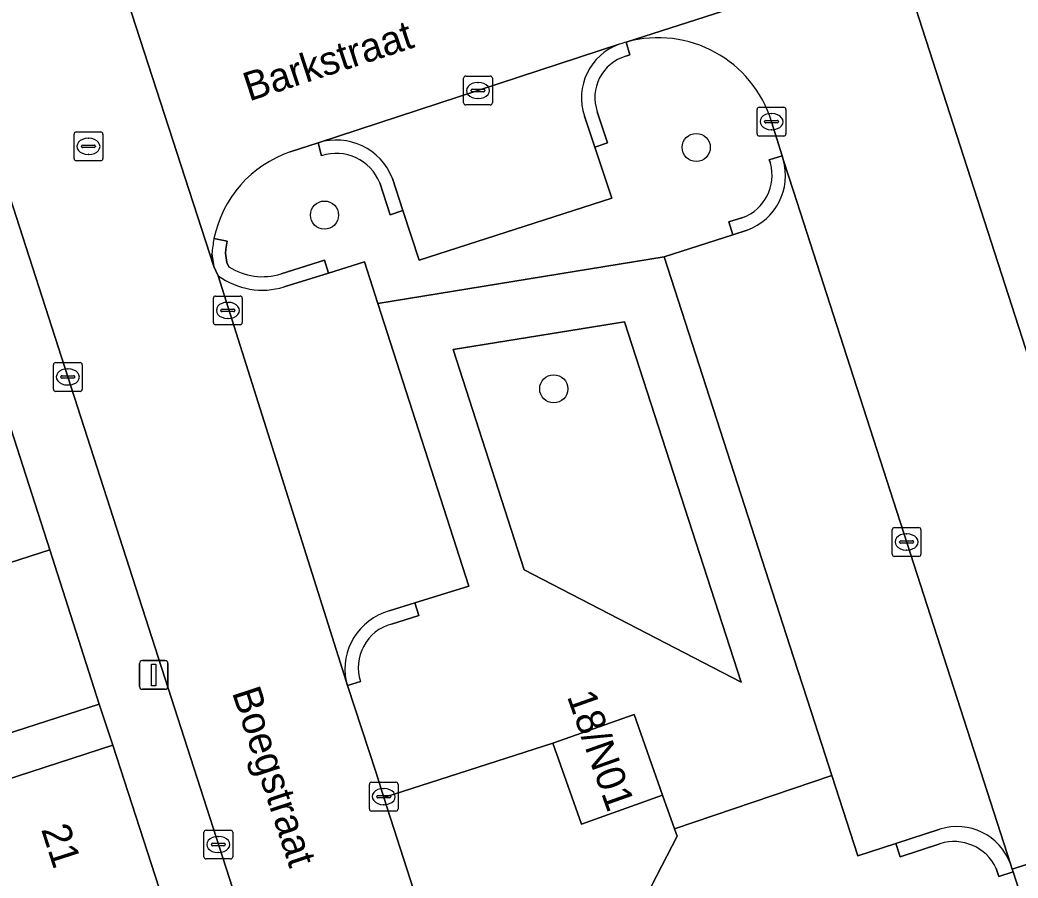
# Model space of a CAD drawing. Extents: x 159371 to 159986, y 382987 to 383597.
# Drawn here: x 159473.09 to 159507.81, y 383319.61 to 383349.44 of the extents above; entities that cross this region are included whole.
import ezdxf

# ---------------------------------------------------------------- set-up
doc = ezdxf.new("R2010")
doc.units = 0
for name, color, linetype in [('IMGEO_Boom', 7, 'Continuous'), ('IMGEO_Groenvoorziening', 7, 'Continuous'), ('IMGEO_Kolk', 7, 'Continuous'), ('IMGEO_Lichtmast', 7, 'Continuous'), ('IMGEO_Openbare_ruimte_label', 7, 'Continuous'), ('IMGEO_Pand', 7, 'Continuous'), ('IMGEO_Pand_nummerreeks', 7, 'Continuous'), ('IMGEO_Parkeervlak_open', 7, 'Continuous'), ('IMGEO_Rijbaan_lokaal_open', 7, 'Continuous'), ('IMGEO_Rioolput', 7, 'Continuous'), ('IMGEO_Voetpad_open', 7, 'Continuous')]:
    doc.layers.add(name, color=color, linetype=linetype)

msp = doc.modelspace()

# ---------------------------------------------------------------- linework, layer by layer
at = {"layer": 'IMGEO_Boom'}
for centre in [(159496.617, 383345.01), (159483.685, 383342.659), (159491.659, 383336.618)]:
    msp.add_circle(centre, 0.489, dxfattribs=at)
at = {"layer": 'IMGEO_Groenvoorziening'}
for points in [[(159494.182, 383348.675), (159494.307, 383348.225), (159494.162, 383348.182)], [(159493.175, 383346.249), (159493.532, 383345.171), (159493.089, 383345.024), (159493.677, 383343.248), (159486.984, 383341.088), (159486.415, 383342.814)], [(159499.196, 383344.46), (159499.156, 383344.583), (159499.601, 383344.723), (159499.237, 383345.904)], [(159483.583, 383344.719), (159483.466, 383345.171), (159482.492, 383344.854)], [(159486.415, 383342.814), (159485.972, 383342.668), (159485.606, 383343.777)], [(159482.176, 383340.618), (159483.687, 383341.089), (159483.826, 383340.644), (159485.072, 383341.032), (159485.541, 383339.58), (159495.497, 383341.203), (159497.889, 383341.976), (159497.745, 383342.42), (159498.235, 383342.578)], [(159479.841, 383341.841), (159480.298, 383341.748), (159480.273, 383341.609), (159480.253, 383341.469), (159480.239, 383341.329), (159480.288, 383341.009), (159480.358, 383340.862)], [(159500.626, 383325.36), (159500, 383327.293), (159495.497, 383341.203), (159485.541, 383339.58), (159488.71, 383329.763), (159486.828, 383329.174), (159486.966, 383328.732), (159486.014, 383328.439)], [(159484.933, 383326.446), (159484.484, 383326.299), (159485.48, 383323.262), (159485.755, 383322.408), (159491.627, 383324.299), (159494.453, 383325.298), (159495.447, 383322.487), (159495.858, 383321.325), (159501.334, 383323.171), (159500.626, 383325.36)], [(159505.094, 383320.803), (159503.712, 383320.352), (159503.564, 383320.811), (159502.237, 383320.383), (159501.334, 383323.171), (159495.858, 383321.325), (159495.949, 383321.067), (159494.157, 383317.584), (159497.271, 383315.986), (159500, 383316.88), (159501.761, 383317.457), (159503.231, 383313.074), (159509.191, 383315.017), (159508.463, 383317.266), (159507.635, 383319.824)], [(159507.635, 383319.824), (159507.142, 383319.664), (159507.051, 383319.945)]]:
    msp.add_lwpolyline(points, dxfattribs=at)
for points in [[(159498.18, 383326.423), (159494.123, 383338.953), (159488.159, 383337.981), (159490.629, 383330.329)], [(159490.629, 383330.329), (159488.159, 383337.981), (159494.123, 383338.953), (159498.18, 383326.423)]]:
    msp.add_lwpolyline(points, close=True, dxfattribs=at)
for centre, radius, start, end in [((159495.287, 383344.694), 4.131, 17.0256, 105.514), ((159494.593, 383346.744), 1.502, 106.674, 199.2278), ((159483.788, 383341.041), 4.027, 108.7711, 168.5427), ((159484.1, 383343.185), 1.619, 21.4513, 108.6111), ((159497.695, 383344.04), 1.559, 290.2668, 15.633), ((159481.524, 383342.657), 2.14, 236.9844, 287.7273), ((159486.428, 383326.925), 1.57, 105.2983, 197.751), ((159505.582, 383319.256), 1.622, 25.1356, 107.5166)]:
    msp.add_arc(centre, radius, start, end, dxfattribs=at)
at = {"layer": 'IMGEO_Kolk'}
for p, q in [((159488.6, 383347.49), (159489.452, 383347.49)), ((159488.525, 383346.564), (159488.525, 383347.416)), ((159489.013, 383347.27), (159489.038, 383347.27)), ((159489.526, 383347.416), (159489.526, 383346.564)), ((159488.784, 383346.984), (159488.784, 383346.996)), ((159489.222, 383346.947), (159488.824, 383346.947)), ((159488.827, 383347.033), (159489.225, 383347.033)), ((159489.268, 383346.996), (159489.268, 383346.984)), ((159489.452, 383346.49), (159488.6, 383346.49)), ((159489.036, 383346.71), (159489.011, 383346.71)), ((159498.809, 383346.407), (159499.661, 383346.407)), ((159498.734, 383345.481), (159498.734, 383346.333)), ((159499.222, 383346.187), (159499.247, 383346.187)), ((159499.735, 383346.333), (159499.735, 383345.481)), ((159498.993, 383345.901), (159498.993, 383345.913)), ((159499.431, 383345.864), (159499.033, 383345.864)), ((159499.036, 383345.95), (159499.434, 383345.95)), ((159499.477, 383345.913), (159499.477, 383345.901)), ((159499.661, 383345.407), (159498.809, 383345.407)), ((159499.245, 383345.627), (159499.22, 383345.627)), ((159479.898, 383339.845), (159480.75, 383339.845)), ((159479.823, 383338.919), (159479.823, 383339.771)), ((159480.311, 383339.625), (159480.336, 383339.625)), ((159480.824, 383339.771), (159480.824, 383338.919)), ((159480.082, 383339.339), (159480.082, 383339.351)), ((159480.52, 383339.302), (159480.122, 383339.302)), ((159480.125, 383339.388), (159480.523, 383339.388)), ((159480.566, 383339.351), (159480.566, 383339.339)), ((159480.75, 383338.845), (159479.898, 383338.845)), ((159480.334, 383339.065), (159480.309, 383339.065)), ((159474.256, 383336.605), (159474.256, 383337.457)), ((159474.331, 383337.531), (159475.183, 383337.531)), ((159475.257, 383337.457), (159475.257, 383336.605)), ((159474.515, 383337.025), (159474.515, 383337.037)), ((159474.558, 383337.074), (159474.956, 383337.074)), ((159474.744, 383337.311), (159474.769, 383337.311)), ((159474.999, 383337.037), (159474.999, 383337.025)), ((159474.953, 383336.988), (159474.555, 383336.988)), ((159474.767, 383336.751), (159474.742, 383336.751)), ((159475.183, 383336.531), (159474.331, 383336.531)), ((159503.432, 383330.868), (159503.432, 383331.72)), ((159503.507, 383331.794), (159504.359, 383331.794)), ((159503.92, 383331.574), (159503.945, 383331.574)), ((159504.433, 383331.72), (159504.433, 383330.868)), ((159503.691, 383331.288), (159503.691, 383331.3)), ((159504.129, 383331.251), (159503.731, 383331.251)), ((159503.734, 383331.337), (159504.132, 383331.337)), ((159504.175, 383331.3), (159504.175, 383331.288)), ((159504.359, 383330.794), (159503.507, 383330.794)), ((159503.943, 383331.014), (159503.918, 383331.014)), ((159485.245, 383322.014), (159485.245, 383322.866)), ((159485.32, 383322.94), (159486.172, 383322.94)), ((159486.246, 383322.866), (159486.246, 383322.014)), ((159485.547, 383322.483), (159485.945, 383322.483)), ((159485.733, 383322.72), (159485.758, 383322.72)), ((159485.504, 383322.434), (159485.504, 383322.446)), ((159485.942, 383322.397), (159485.544, 383322.397)), ((159485.756, 383322.16), (159485.731, 383322.16)), ((159485.988, 383322.446), (159485.988, 383322.434)), ((159486.172, 383321.94), (159485.32, 383321.94)), ((159479.491, 383320.348), (159479.491, 383321.2)), ((159479.566, 383321.274), (159480.418, 383321.274)), ((159480.492, 383321.2), (159480.492, 383320.348)), ((159479.75, 383320.768), (159479.75, 383320.78)), ((159480.188, 383320.731), (159479.79, 383320.731)), ((159479.793, 383320.817), (159480.191, 383320.817)), ((159479.979, 383321.054), (159480.004, 383321.054)), ((159480.234, 383320.78), (159480.234, 383320.768)), ((159480.002, 383320.494), (159479.977, 383320.494)), ((159480.418, 383320.274), (159479.566, 383320.274))]:
    msp.add_line(p, q, dxfattribs=at)
for points in [[(159488.6, 383347.49), (159489.452, 383347.49)], [(159488.525, 383346.564), (159488.525, 383347.416)], [(159489.526, 383347.416), (159489.526, 383346.564)], [(159489.452, 383346.49), (159488.6, 383346.49)], [(159498.809, 383346.407), (159499.661, 383346.407)], [(159498.734, 383345.481), (159498.734, 383346.333)], [(159499.735, 383346.333), (159499.735, 383345.481)], [(159499.661, 383345.407), (159498.809, 383345.407)], [(159479.898, 383339.845), (159480.75, 383339.845)], [(159479.823, 383338.919), (159479.823, 383339.771)], [(159480.824, 383339.771), (159480.824, 383338.919)], [(159480.75, 383338.845), (159479.898, 383338.845)], [(159474.256, 383336.605), (159474.256, 383337.457)], [(159474.331, 383337.531), (159475.183, 383337.531)], [(159475.257, 383337.457), (159475.257, 383336.605)], [(159475.183, 383336.531), (159474.331, 383336.531)], [(159503.432, 383330.868), (159503.432, 383331.72)], [(159503.507, 383331.794), (159504.359, 383331.794)], [(159504.433, 383331.72), (159504.433, 383330.868)], [(159504.359, 383330.794), (159503.507, 383330.794)], [(159485.245, 383322.014), (159485.245, 383322.866)], [(159485.32, 383322.94), (159486.172, 383322.94)], [(159486.246, 383322.866), (159486.246, 383322.014)], [(159486.172, 383321.94), (159485.32, 383321.94)], [(159479.491, 383320.348), (159479.491, 383321.2)], [(159479.566, 383321.274), (159480.418, 383321.274)], [(159480.492, 383321.2), (159480.492, 383320.348)], [(159480.418, 383320.274), (159479.566, 383320.274)]]:
    msp.add_lwpolyline(points, dxfattribs=at)
for centre, radius, start, end in [((159488.602, 383347.414), 0.0765, 91.552, 178.448), ((159488.602, 383347.414), 0.0765, 91.552, 178.448), ((159489.45, 383347.414), 0.0765, 1.552, 88.448), ((159489.45, 383347.414), 0.0765, 1.552, 88.448), ((159488.824, 383346.993), 0.0403, 85.8775, 175.7526), ((159488.821, 383346.983), 0.0366, 178.938, 274.7102), ((159489.225, 383346.99), 0.043, 264.8664, 352.4533), ((159489.229, 383346.995), 0.0386, 1.7309, 96.639), ((159488.602, 383346.566), 0.0765, 181.552, 268.448), ((159488.602, 383346.566), 0.0765, 181.552, 268.448), ((159489.45, 383346.566), 0.0765, 271.552, 358.448), ((159489.45, 383346.566), 0.0765, 271.552, 358.448), ((159498.811, 383346.331), 0.0765, 91.552, 178.448), ((159498.811, 383346.331), 0.0765, 91.552, 178.448), ((159499.659, 383346.331), 0.0765, 1.552, 88.448), ((159499.659, 383346.331), 0.0765, 1.552, 88.448), ((159499.033, 383345.91), 0.0403, 85.8775, 175.7526), ((159499.03, 383345.9), 0.0366, 178.938, 274.7102), ((159499.434, 383345.907), 0.043, 264.8664, 352.4533), ((159499.438, 383345.912), 0.0386, 1.7309, 96.639), ((159498.811, 383345.483), 0.0765, 181.552, 268.448), ((159498.811, 383345.483), 0.0765, 181.552, 268.448), ((159499.659, 383345.483), 0.0765, 271.552, 358.448), ((159499.659, 383345.483), 0.0765, 271.552, 358.448), ((159479.9, 383339.769), 0.0765, 91.552, 178.448), ((159479.9, 383339.769), 0.0765, 91.552, 178.448), ((159480.748, 383339.769), 0.0765, 1.552, 88.448), ((159480.748, 383339.769), 0.0765, 1.552, 88.448), ((159480.122, 383339.348), 0.0403, 85.8775, 175.7526), ((159480.119, 383339.338), 0.0366, 178.938, 274.7102), ((159480.523, 383339.345), 0.043, 264.8664, 352.4533), ((159480.527, 383339.35), 0.0386, 1.7309, 96.639), ((159479.9, 383338.921), 0.0765, 181.552, 268.448), ((159479.9, 383338.921), 0.0765, 181.552, 268.448), ((159480.748, 383338.921), 0.0765, 271.552, 358.448), ((159480.748, 383338.921), 0.0765, 271.552, 358.448), ((159474.333, 383337.455), 0.0765, 91.552, 178.448), ((159474.333, 383337.455), 0.0765, 91.552, 178.448), ((159475.181, 383337.455), 0.0765, 1.552, 88.448), ((159475.181, 383337.455), 0.0765, 1.552, 88.448), ((159474.555, 383337.034), 0.0403, 85.8775, 175.7526), ((159474.96, 383337.036), 0.0386, 1.7309, 96.639), ((159474.552, 383337.024), 0.0366, 178.938, 274.7102), ((159474.956, 383337.031), 0.043, 264.8664, 352.4533), ((159474.333, 383336.607), 0.0765, 181.552, 268.448), ((159474.333, 383336.607), 0.0765, 181.552, 268.448), ((159475.181, 383336.607), 0.0765, 271.552, 358.448), ((159475.181, 383336.607), 0.0765, 271.552, 358.448), ((159503.509, 383331.718), 0.0765, 91.552, 178.448), ((159503.509, 383331.718), 0.0765, 91.552, 178.448), ((159504.357, 383331.718), 0.0765, 1.552, 88.448), ((159504.357, 383331.718), 0.0765, 1.552, 88.448), ((159503.731, 383331.297), 0.0403, 85.8775, 175.7526), ((159503.728, 383331.287), 0.0366, 178.938, 274.7102), ((159504.132, 383331.294), 0.043, 264.8664, 352.4533), ((159504.136, 383331.299), 0.0386, 1.7309, 96.639), ((159503.509, 383330.87), 0.0765, 181.552, 268.448), ((159503.509, 383330.87), 0.0765, 181.552, 268.448), ((159504.357, 383330.87), 0.0765, 271.552, 358.448), ((159504.357, 383330.87), 0.0765, 271.552, 358.448), ((159485.322, 383322.864), 0.0765, 91.552, 178.448), ((159485.322, 383322.864), 0.0765, 91.552, 178.448), ((159486.17, 383322.864), 0.0765, 1.552, 88.448), ((159486.17, 383322.864), 0.0765, 1.552, 88.448), ((159485.544, 383322.443), 0.0403, 85.8775, 175.7526), ((159485.949, 383322.445), 0.0386, 1.7309, 96.639), ((159485.541, 383322.433), 0.0366, 178.938, 274.7102), ((159485.945, 383322.44), 0.043, 264.8664, 352.4533), ((159485.322, 383322.016), 0.0765, 181.552, 268.448), ((159485.322, 383322.016), 0.0765, 181.552, 268.448), ((159486.17, 383322.016), 0.0765, 271.552, 358.448), ((159486.17, 383322.016), 0.0765, 271.552, 358.448), ((159479.568, 383321.198), 0.0765, 91.552, 178.448), ((159479.568, 383321.198), 0.0765, 91.552, 178.448), ((159480.416, 383321.198), 0.0765, 1.552, 88.448), ((159480.416, 383321.198), 0.0765, 1.552, 88.448), ((159479.79, 383320.777), 0.0403, 85.8775, 175.7526), ((159479.787, 383320.767), 0.0366, 178.938, 274.7102), ((159480.191, 383320.774), 0.043, 264.8664, 352.4533), ((159480.195, 383320.779), 0.0386, 1.7309, 96.639), ((159479.568, 383320.35), 0.0765, 181.552, 268.448), ((159479.568, 383320.35), 0.0765, 181.552, 268.448), ((159480.416, 383320.35), 0.0765, 271.552, 358.448), ((159480.416, 383320.35), 0.0765, 271.552, 358.448)]:
    msp.add_arc(centre, radius, start, end, dxfattribs=at)
for centre, major_axis, ratio, start_param, end_param in [((159489.012, 383346.99), (-0.387, 0.002), 0.722429, 4.712389, 7.853982), ((159489.037, 383346.99), (-0.39, 0.002), 0.717154, 1.570796, 4.712389), ((159499.221, 383345.907), (-0.387, 0.002), 0.722429, 4.712389, 7.853982), ((159499.246, 383345.907), (-0.39, 0.002), 0.717154, 1.570796, 4.712389), ((159480.31, 383339.345), (-0.387, 0.002), 0.722429, 4.712389, 7.853982), ((159480.335, 383339.345), (-0.39, 0.002), 0.717154, 1.570796, 4.712389), ((159474.743, 383337.031), (-0.387, 0.002), 0.722429, 4.712389, 7.853982), ((159474.768, 383337.031), (-0.39, 0.002), 0.717154, 1.570796, 4.712389), ((159503.919, 383331.294), (-0.387, 0.002), 0.722429, 4.712389, 7.853982), ((159503.944, 383331.294), (-0.39, 0.002), 0.717154, 1.570796, 4.712389), ((159485.732, 383322.44), (-0.387, 0.002), 0.722429, 4.712389, 7.853982), ((159485.757, 383322.44), (-0.39, 0.002), 0.717154, 1.570796, 4.712389), ((159479.978, 383320.774), (-0.387, 0.002), 0.722429, 4.712389, 7.853982), ((159480.003, 383320.774), (-0.39, 0.002), 0.717154, 1.570796, 4.712389)]:
    msp.add_ellipse(centre, major_axis=major_axis, ratio=ratio, start_param=start_param, end_param=end_param, dxfattribs=at)
at = {"layer": 'IMGEO_Lichtmast'}
for p, q in [((159477.249, 383326.271), (159477.249, 383327.071)), ((159477.249, 383327.071), (159477.249, 383326.271)), ((159477.349, 383327.171), (159478.139, 383327.171)), ((159478.139, 383327.171), (159477.349, 383327.171)), ((159478.239, 383327.071), (159478.239, 383326.271)), ((159478.239, 383326.271), (159478.239, 383327.071)), ((159478.139, 383326.171), (159477.349, 383326.171)), ((159477.349, 383326.171), (159478.139, 383326.171))]:
    msp.add_line(p, q, dxfattribs=at)
msp.add_lwpolyline([(159477.669, 383327.046), (159477.819, 383327.046), (159477.819, 383326.296), (159477.669, 383326.296), (159477.669, 383327.046)], dxfattribs=at)
for centre, start, end in [((159477.349, 383327.071), 90, 180), ((159477.349, 383327.071), 90, 180), ((159478.139, 383327.071), 0, 90), ((159478.139, 383327.071), 360, 90), ((159477.349, 383326.271), 180, 270), ((159477.349, 383326.271), 180, 270), ((159478.139, 383326.271), 270, 0), ((159478.139, 383326.271), 270, 0)]:
    msp.add_arc(centre, 0.1, start, end, dxfattribs=at)
at = {"layer": 'IMGEO_Pand'}
for points in [[(159472.472, 383336.172), (159464.302, 383333.539), (159461.161, 383332.527), (159462.821, 383327.376), (159465.962, 383328.388), (159474.127, 383331.019)], [(159465.962, 383328.388), (159467.69, 383323.026), (159471.091, 383324.124), (159475.849, 383325.659), (159474.127, 383331.019)], [(159494.453, 383325.298), (159491.627, 383324.299), (159492.621, 383321.488), (159495.447, 383322.487)], [(159469.879, 383316.222), (159478.057, 383318.86), (159476.326, 383324.233), (159471.572, 383322.687), (159468.153, 383321.575)]]:
    msp.add_lwpolyline(points, close=True, dxfattribs=at)
at = {"layer": 'IMGEO_Parkeervlak_open'}
for points in [[(159493.936, 383348.598), (159483.466, 383345.171)], [(159486.045, 383343.935), (159486.415, 383342.814), (159486.984, 383341.088), (159493.677, 383343.248), (159493.089, 383345.024), (159492.733, 383346.099)], [(159500, 383343.486), (159499.642, 383344.595)], [(159507.545, 383320.103), (159500, 383343.486)], [(159498.387, 383342.137), (159497.889, 383341.976), (159495.497, 383341.203), (159500, 383327.293), (159500.626, 383325.36), (159501.334, 383323.171), (159502.237, 383320.383), (159503.564, 383320.811), (159505.093, 383321.304)], [(159485.541, 383339.58), (159485.072, 383341.032), (159483.826, 383340.644), (159482.281, 383340.162)], [(159479.991, 383340.549), (159484.434, 383326.453)], [(159485.936, 383328.895), (159486.828, 383329.174), (159488.71, 383329.763), (159485.541, 383339.58)]]:
    msp.add_lwpolyline(points, dxfattribs=at)
for centre, radius, start, end in [((159494.595, 383346.742), 1.97, 109.5393, 199.049), ((159484.098, 383343.181), 2.088, 21.171, 107.6163), ((159497.697, 383344.038), 2.023, 289.9334, 15.9709), ((159481.524, 383342.652), 2.603, 233.9114, 286.9044), ((159486.501, 383326.865), 2.108, 105.5514, 191.2597), ((159505.698, 383319.435), 1.964, 19.8814, 107.9269)]:
    msp.add_arc(centre, radius, start, end, dxfattribs=at)
at = {"layer": 'IMGEO_Rijbaan_lokaal_open'}
for points in [[(159464.643, 383368.374), (159482.73, 383312.288), (159488.424, 383314.124), (159488.383, 383314.25), (159485.755, 383322.408), (159485.48, 383323.262), (159484.484, 383326.299), (159484.434, 383326.453), (159479.991, 383340.549), (159479.838, 383340.87), (159476.124, 383352.314)], [(159494.182, 383348.675), (159503.646, 383351.717), (159506.376, 383352.592), (159517.827, 383356.31)], [(159476.124, 383352.314), (159479.838, 383340.87), (159479.77, 383341.31)], [(159503.646, 383351.717), (159494.182, 383348.675)], [(159499.237, 383345.904), (159499.601, 383344.723), (159499.642, 383344.595), (159500, 383343.486), (159507.545, 383320.103), (159507.604, 383319.921), (159513.324, 383321.769), (159503.646, 383351.717)], [(159482.492, 383344.854), (159483.466, 383345.171), (159493.936, 383348.598)]]:
    msp.add_lwpolyline(points, dxfattribs=at)
msp.add_lwpolyline([(159513.324, 383321.769), (159507.604, 383319.921), (159507.635, 383319.824), (159508.463, 383317.266), (159514.182, 383319.114)], close=True, dxfattribs=at)
for centre, radius, start, end in [((159495.493, 383344.056), 4.801, 105.8423, 108.9188), ((159495.287, 383344.694), 4.131, 17.0256, 105.514), ((159483.788, 383341.041), 4.027, 108.7711, 168.5427), ((159483.925, 383341.025), 4.164, 168.6962, 176.0722)]:
    msp.add_arc(centre, radius, start, end, dxfattribs=at)
at = {"layer": 'IMGEO_Rioolput'}
for p, q in [((159474.975, 383344.622), (159474.975, 383345.474)), ((159475.05, 383345.548), (159475.902, 383345.548)), ((159475.976, 383345.474), (159475.976, 383344.622)), ((159475.234, 383345.042), (159475.234, 383345.054)), ((159475.277, 383345.091), (159475.675, 383345.091)), ((159475.463, 383345.328), (159475.488, 383345.328)), ((159475.718, 383345.054), (159475.718, 383345.042)), ((159475.672, 383345.005), (159475.274, 383345.005)), ((159475.486, 383344.768), (159475.461, 383344.768)), ((159475.902, 383344.548), (159475.05, 383344.548))]:
    msp.add_line(p, q, dxfattribs=at)
for points in [[(159474.975, 383344.622), (159474.975, 383345.474)], [(159475.05, 383345.548), (159475.902, 383345.548)], [(159475.976, 383345.474), (159475.976, 383344.622)], [(159475.902, 383344.548), (159475.05, 383344.548)]]:
    msp.add_lwpolyline(points, dxfattribs=at)
for centre, radius, start, end in [((159475.052, 383345.472), 0.0765, 91.552, 178.448), ((159475.052, 383345.472), 0.0765, 91.552, 178.448), ((159475.9, 383345.472), 0.0765, 1.552, 88.448), ((159475.9, 383345.472), 0.0765, 1.552, 88.448), ((159475.274, 383345.051), 0.0403, 85.8775, 175.7526), ((159475.271, 383345.041), 0.0366, 178.938, 274.7102), ((159475.675, 383345.048), 0.043, 264.8664, 352.4533), ((159475.679, 383345.053), 0.0386, 1.7309, 96.639), ((159475.052, 383344.624), 0.0765, 181.552, 268.448), ((159475.052, 383344.624), 0.0765, 181.552, 268.448), ((159475.9, 383344.624), 0.0765, 271.552, 358.448), ((159475.9, 383344.624), 0.0765, 271.552, 358.448)]:
    msp.add_arc(centre, radius, start, end, dxfattribs=at)
for centre, major_axis, ratio, start_param, end_param in [((159475.462, 383345.048), (-0.387, 0.002), 0.722429, 4.712389, 7.853982), ((159475.487, 383345.048), (-0.39, 0.002), 0.717154, 1.570796, 4.712389)]:
    msp.add_ellipse(centre, major_axis=major_axis, ratio=ratio, start_param=start_param, end_param=end_param, dxfattribs=at)
at = {"layer": 'IMGEO_Voetpad_open'}
for points in [[(159497.907, 383277.902), (159491.962, 383283.659), (159483.583, 383309.643), (159482.73, 383312.288), (159464.643, 383368.374), (159462.363, 383367.551), (159464.145, 383362.091), (159465.857, 383356.763), (159467.521, 383351.582), (159469.167, 383346.458), (159470.822, 383341.306), (159472.472, 383336.172), (159474.127, 383331.019), (159475.849, 383325.659), (159476.326, 383324.233), (159478.057, 383318.86), (159479.71, 383313.73), (159481.375, 383308.56), (159483.031, 383303.42), (159484.708, 383298.213), (159486.361, 383293.083), (159488.026, 383287.914), (159489.673, 383282.802), (159491.407, 383277.42)], [(159506.376, 383352.592), (159503.646, 383351.717), (159513.324, 383321.769), (159514.182, 383319.114), (159521.99, 383294.954)], [(159494.162, 383348.182), (159494.307, 383348.225), (159494.182, 383348.675)], [(159492.733, 383346.099), (159493.089, 383345.024), (159493.532, 383345.171), (159493.175, 383346.249)], [(159483.466, 383345.171), (159483.583, 383344.719)], [(159499.642, 383344.595), (159499.601, 383344.723), (159499.156, 383344.583), (159499.196, 383344.46)], [(159485.606, 383343.777), (159485.972, 383342.668), (159486.415, 383342.814), (159486.045, 383343.935)], [(159498.235, 383342.578), (159497.745, 383342.42), (159497.889, 383341.976), (159498.387, 383342.137)], [(159480.358, 383340.862), (159480.288, 383341.009), (159480.239, 383341.329), (159480.253, 383341.469), (159480.273, 383341.609), (159480.298, 383341.748), (159479.841, 383341.841)], [(159479.77, 383341.31), (159479.838, 383340.87), (159479.991, 383340.549)], [(159483.826, 383340.644), (159483.687, 383341.089), (159482.176, 383340.618)], [(159482.281, 383340.162), (159483.826, 383340.644)], [(159486.014, 383328.439), (159486.966, 383328.732), (159486.828, 383329.174), (159485.936, 383328.895)], [(159484.434, 383326.453), (159484.484, 383326.299), (159484.933, 383326.446)], [(159471.572, 383322.687), (159476.326, 383324.233), (159475.849, 383325.659), (159471.091, 383324.124)], [(159497.271, 383315.986), (159494.157, 383317.584), (159495.949, 383321.067), (159495.858, 383321.325), (159495.447, 383322.487), (159492.621, 383321.488), (159491.627, 383324.299), (159485.755, 383322.408), (159488.383, 383314.25), (159488.424, 383314.124), (159489.276, 383311.479), (159489.33, 383311.312), (159494.936, 383313.157), (159494.276, 383315.161), (159500, 383312.201), (159500.241, 383312.076), (159501.34, 383311.507), (159504.318, 383309.883), (159505.212, 383307.15), (159506.345, 383307.525), (159509.203, 383308.471)], [(159505.093, 383321.304), (159503.564, 383320.811), (159503.712, 383320.352), (159505.094, 383320.803)], [(159507.051, 383319.945), (159507.142, 383319.664), (159507.635, 383319.824), (159507.604, 383319.921), (159507.545, 383320.103)]]:
    msp.add_lwpolyline(points, dxfattribs=at)
for centre, radius, start, end in [((159494.595, 383346.742), 1.97, 109.5393, 199.049), ((159495.493, 383344.056), 4.801, 105.8423, 108.9188), ((159494.593, 383346.744), 1.502, 106.674, 199.2278), ((159484.098, 383343.181), 2.088, 21.171, 107.6163), ((159484.1, 383343.185), 1.619, 21.4513, 108.6111), ((159497.695, 383344.04), 1.559, 290.2668, 15.633), ((159497.697, 383344.038), 2.023, 289.9334, 15.9709), ((159483.925, 383341.025), 4.164, 168.6962, 176.0722), ((159481.524, 383342.657), 2.14, 236.9844, 287.7273), ((159481.524, 383342.652), 2.603, 233.9114, 286.9044), ((159486.501, 383326.865), 2.108, 105.5514, 191.2597), ((159486.428, 383326.925), 1.57, 105.2983, 197.751), ((159505.698, 383319.435), 1.964, 19.8814, 107.9269), ((159505.582, 383319.256), 1.622, 25.1356, 107.5166)]:
    msp.add_arc(centre, radius, start, end, dxfattribs=at)

# ---------------------------------------------------------------- texts
at = {"layer": 'IMGEO_Openbare_ruimte_label'}
for s, rotation, p in [('Barkstraat', 18.1268, (159481.064, 383346.606)), ('Boegstraat', 288.1813, (159480.461, 383326.065))]:
    msp.add_text(s, height=1, rotation=rotation, dxfattribs=at).set_placement(p)
at = {"layer": 'IMGEO_Pand_nummerreeks'}
for s, rotation, p in [('18/N01', 289.4746, (159492.112, 383325.928)), ('21', 287.8566, (159473.824, 383321.305))]:
    msp.add_text(s, height=1, rotation=rotation, dxfattribs=at).set_placement(p)

doc.saveas('drawing.dxf')
